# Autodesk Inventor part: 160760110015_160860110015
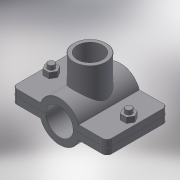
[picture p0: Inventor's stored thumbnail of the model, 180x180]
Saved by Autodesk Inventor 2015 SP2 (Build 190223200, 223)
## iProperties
Created: 2017-05
Part Number: 160760110015_160860110015
Material: Generic
Description: PLASSON SADDLE 110-1.1/2"
Document SubType Name: Modeling
Designer: KIM
Density: 1 g/cm^3
Appearance: Default
Author: KIM
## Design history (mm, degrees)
derived "16076.ipt"
feature "Solid1::16076.ipt"
feature "Solid2::16076.ipt"
tag "TaggingFeature1"
body "Solid1"
other parameters: "d0" = 121, "d1" = 165, "d2" = 55, "d4" = 116, "d5" = 0, "d6" = 8.25, "d7" = 165, "d8" = 0.1, "d10" = 0, "d11" = 1.1, "d14" = 58.2985, "d20" = 1.1, "d23" = 1.1, "d36" = 13, "d37" = 10.4, "d38" = 63, "d39" = 0, "d40" = 3, "d41" = 5, "d42" = 0, "d43" = 8, "d44" = 3, "d45" = 0, "d46" = 1.1, "d51" = 92, "d52" = 44.845, "d53" = 25, "d54" = 0, "d57" = 0, "d58" = 118.8, "d60" = 0, "d62" = 13, "d63" = 10.4, "d66" = 95.2, "G_" = 44.845, "A_" = 92, "L_" = 165, "L_1" = 116, "l_2" = 25
